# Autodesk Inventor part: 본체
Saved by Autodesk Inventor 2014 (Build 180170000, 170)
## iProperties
Created: 2026-07
Part Number: 본체
Material: 일반
Document SubType Name: Modeling
Designer: dg
Density: 1 g/cm^3
Appearance: 기본값
Author: dg
Author: jhkim
Creation Date: 2026-07-02
Sending System: Autodesk Inventor 2027
Preprocessor: ST-DEVELOPER v20.1
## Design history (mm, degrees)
node "본체1"
node "솔리드1"
node "기준1"
